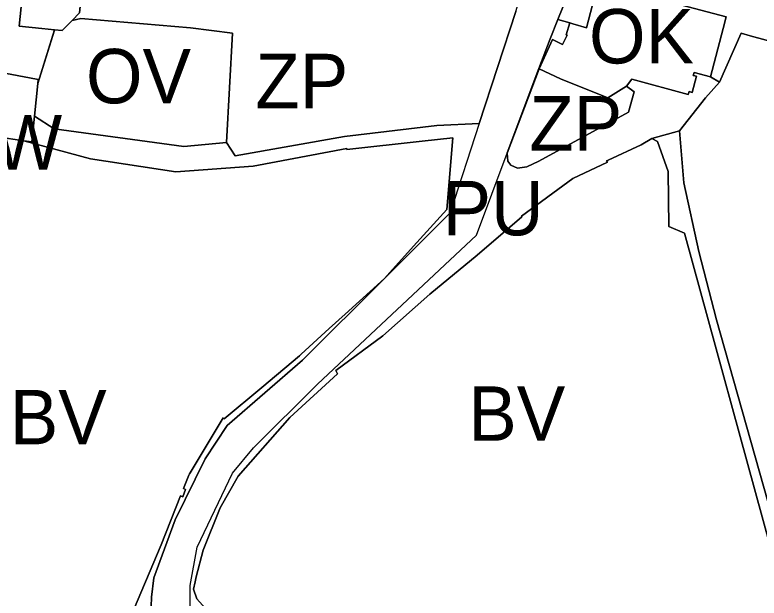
# Model space of a CAD drawing. Extents: x -555509 to -553005, y -1186756 to -1182560.
# Drawn here: x -554643.5 to -554451.9, y -1184692.3 to -1184542.3 of the extents above; entities that cross this region are included whole.
import ezdxf

# ---------------------------------------------------------------- set-up
doc = ezdxf.new("R2010")
doc.units = 0
for name, color, linetype in [('Level 15', 7, 'Continuous'), ('Level 59', 7, 'Continuous'), ('OBRYS_PLOCH', 7, 'Continuous'), ('stav_BV', 7, 'Continuous'), ('stav_DS', 7, 'Continuous'), ('stav_OK', 7, 'Continuous'), ('stav_OV', 7, 'Continuous'), ('stav_PU', 7, 'Continuous'), ('stav_TW', 7, 'Continuous'), ('stav_ZP', 7, 'Continuous')]:
    doc.layers.add(name, color=color, linetype=linetype)

msp = doc.modelspace()

# ---------------------------------------------------------------- linework, layer by layer
at = {"layer": 'Level 15'}
for p, q in [((-554462.1, -1184559.62), (-554464.39, -1184558.17)), ((-554633.37, -1184571.61), (-554638.48, -1184568.37)), ((-554600.05, -1184576.16), (-554633.37, -1184571.61)), ((-554479.48, -1184574.05), (-554472.4, -1184572.07)), ((-554589.05, -1184575.07), (-554600.05, -1184576.16))]:
    msp.add_line(p, q, dxfattribs=at)
for points in [[(-554431.8, -1184526.75), (-554468.49, -1184510.58), (-554512.11, -1184515.49), (-554501.82, -1184520.64), (-554490.14, -1184521.71), (-554496.01, -1184528.61), (-554497.62, -1184530.51), (-554502.44, -1184540.28), (-554503.73, -1184543.47), (-554500.65, -1184544.34), (-554499.87, -1184544.56), (-554496.29, -1184545.6), (-554493.28, -1184534.02), (-554460.33, -1184542.77), (-554461.09, -1184545.8), (-554464.39, -1184558.17), (-554462.1, -1184559.62), (-554456.48, -1184546.98), (-554454.18, -1184547.62), (-554450.06, -1184548.76)], [(-554503.73, -1184543.47), (-554502.44, -1184540.28), (-554497.62, -1184530.51), (-554496.01, -1184528.61), (-554490.14, -1184521.71), (-554501.82, -1184520.64)], [(-554647.61, -1184556.97), (-554637.95, -1184558.83), (-554637.55, -1184558.91), (-554637.65, -1184559.89), (-554633.35, -1184546.14), (-554636.54, -1184545.76), (-554642.43, -1184545.2), (-554641.91, -1184540.17)], [(-554514.53, -1184541.36), (-554523.93, -1184570.22), (-554534.86, -1184570.77), (-554558.65, -1184573.59), (-554586.8, -1184578.55), (-554589.05, -1184575.07)], [(-554503.73, -1184543.47), (-554505.72, -1184548.39), (-554508.61, -1184556.1), (-554508.55, -1184556.13)], [(-554508.55, -1184556.13), (-554508.61, -1184556.1), (-554505.72, -1184548.39), (-554503.73, -1184543.47)], [(-554500.65, -1184544.34), (-554503.73, -1184543.47)], [(-554502.51, -1184549.89), (-554501.31, -1184547.46), (-554501.53, -1184547.4), (-554500.65, -1184544.34)], [(-554508.55, -1184556.13), (-554505.11, -1184548.62), (-554502.51, -1184549.89)], [(-554511.73, -1184581.35), (-554514.1, -1184581.73), (-554515.78, -1184580.97), (-554516.62, -1184579.9), (-554516.77, -1184577.83), (-554508.55, -1184556.13)], [(-554464.39, -1184558.17), (-554468.61, -1184557.07), (-554468.82, -1184557.84), (-554468.04, -1184558.05), (-554469.15, -1184562.23), (-554469.92, -1184562.02), (-554470.11, -1184562.71), (-554484.65, -1184558.85), (-554486.05, -1184560.65)], [(-554472.4, -1184572.07), (-554465.7, -1184563.62), (-554462.1, -1184559.62)], [(-554486.05, -1184560.65), (-554484.04, -1184562.05), (-554485.49, -1184567.31), (-554508.61, -1184579.9), (-554511.73, -1184581.35)], [(-554638.48, -1184568.37), (-554639.13, -1184574.95), (-554641.22, -1184574.69)], [(-554479.48, -1184574.05), (-554472.4, -1184572.07)], [(-554445.16, -1184683.29), (-554462.84, -1184620.73), (-554467.41, -1184603.12), (-554471.22, -1184585.47), (-554472.4, -1184572.07), (-554479.48, -1184574.05), (-554478.02, -1184574.88), (-554475.32, -1184582.57), (-554475.11, -1184596.75), (-554471.13, -1184598.47), (-554448.83, -1184679.59)], [(-554641.22, -1184574.69), (-554624.01, -1184579.27), (-554602.06, -1184582.66), (-554582.17, -1184581.21), (-554558.05, -1184576.67), (-554558.06, -1184576.89), (-554538.67, -1184574.78), (-554530.71, -1184573.92), (-554532.3, -1184592.32), (-554540.01, -1184600.84), (-554546.31, -1184607.82)], [(-554548.81, -1184624.84), (-554536.63, -1184614.15), (-554524.49, -1184604.09), (-554512.94, -1184594.19), (-554513.06, -1184594.03), (-554499.86, -1184584.38), (-554490.9, -1184580.13), (-554491.15, -1184579.84), (-554490.74, -1184579.65), (-554482.25, -1184575.67), (-554479.48, -1184574.05)], [(-554546.31, -1184607.82), (-554548.33, -1184610.06), (-554558.48, -1184619.25), (-554562.59, -1184622.97), (-554569.82, -1184629.59), (-554570.26, -1184630), (-554579.97, -1184638.12), (-554589.61, -1184646.18), (-554589.92, -1184645.93), (-554598.4, -1184660.08), (-554598.56, -1184660.35), (-554598.7, -1184660.7), (-554600.08, -1184664.15), (-554599.55, -1184664.36), (-554600.31, -1184666.27), (-554600.84, -1184666.06), (-554605.86, -1184678.63), (-554613.93, -1184697.63)], [(-554560.44, -1184634.63), (-554560.91, -1184633.73), (-554548.81, -1184624.84)], [(-554586.04, -1184660.92), (-554572.69, -1184645.88), (-554560.44, -1184634.63)], [(-554596.64, -1184692.56), (-554597.52, -1184690.07), (-554597.1, -1184688.17), (-554596.82, -1184686.83), (-554595.05, -1184680.03), (-554590.62, -1184669.11), (-554586.04, -1184660.92)]]:
    msp.add_lwpolyline(points, dxfattribs=at)
at = {"layer": 'OBRYS_PLOCH'}
for p, q in [((-554503.73, -1184543.47), (-554502.44, -1184540.28)), ((-554514.53, -1184541.36), (-554523.93, -1184570.22)), ((-554628.76, -1184543.68), (-554631.37, -1184546.32)), ((-554505.72, -1184548.39), (-554503.73, -1184543.47)), ((-554633.44, -1184546.43), (-554637.65, -1184559.89)), ((-554633.35, -1184546.14), (-554633.44, -1184546.43)), ((-554631.37, -1184546.32), (-554633.35, -1184546.14)), ((-554508.61, -1184556.1), (-554505.72, -1184548.39)), ((-554516.75, -1184577.78), (-554508.61, -1184556.1)), ((-554503.03, -1184558.71), (-554508.55, -1184556.13)), ((-554638.48, -1184568.37), (-554637.65, -1184559.89)), ((-554637.65, -1184559.89), (-554638.48, -1184568.37)), ((-554638.48, -1184568.37), (-554633.37, -1184571.61)), ((-554633.37, -1184571.61), (-554600.05, -1184576.16)), ((-554523.93, -1184570.22), (-554531.42, -1184593.24)), ((-554523.93, -1184570.22), (-554523.93, -1184570.22)), ((-554652.51, -1184573.02), (-554641.22, -1184574.69)), ((-554641.22, -1184574.69), (-554652.51, -1184573.02)), ((-554600.05, -1184576.16), (-554589.05, -1184575.07)), ((-554524.68, -1184598.92), (-554516.77, -1184577.83)), ((-554531.42, -1184593.24), (-554548.33, -1184610.06)), ((-554565.59, -1184637.29), (-554524.68, -1184598.92)), ((-554548.33, -1184610.06), (-554569.5, -1184631.1)), ((-554569.5, -1184631.1), (-554548.33, -1184610.06)), ((-554569.5, -1184631.1), (-554588.87, -1184647.93)), ((-554588.87, -1184647.93), (-554569.5, -1184631.1)), ((-554582.04, -1184653.66), (-554565.59, -1184637.29)), ((-554588.87, -1184647.93), (-554594.53, -1184656.5)), ((-554594.53, -1184656.5), (-554588.87, -1184647.93)), ((-554587.48, -1184660.15), (-554582.04, -1184653.66)), ((-554594.53, -1184656.5), (-554602.26, -1184672.17)), ((-554602.26, -1184672.17), (-554594.53, -1184656.5)), ((-554596.62, -1184679.24), (-554587.48, -1184660.15)), ((-554602.26, -1184672.17), (-554607.73, -1184687.15)), ((-554607.73, -1184687.15), (-554602.26, -1184672.17)), ((-554598.38, -1184689.1), (-554596.62, -1184679.24)), ((-554607.73, -1184687.15), (-554608.32, -1184692.11)), ((-554608.32, -1184692.11), (-554607.73, -1184687.15)), ((-554598.29, -1184712.84), (-554598.38, -1184689.1)), ((-554608.32, -1184692.11), (-554612.53, -1184818.21)), ((-554612.53, -1184818.21), (-554608.32, -1184692.11))]:
    msp.add_line(p, q, dxfattribs=at)
for points in [[(-554589.05, -1184575.07), (-554586.8, -1184578.55), (-554558.65, -1184573.59), (-554534.86, -1184570.77), (-554523.93, -1184570.22), (-554514.53, -1184541.36), (-554512.28, -1184533.93), (-554512.36, -1184531.03), (-554513.65, -1184528.36), (-554517.85, -1184525.31), (-554520.44, -1184524.39), (-554525.17, -1184524.38), (-554532.88, -1184525.38), (-554538.03, -1184526.36), (-554562.63, -1184524.9), (-554588.8, -1184510.03), (-554591.92, -1184508.62), (-554607.58, -1184505.07), (-554615.1, -1184503.37), (-554622.88, -1184503.76)], [(-554623.31, -1184507.89), (-554626.87, -1184541.77), (-554628.76, -1184543.68), (-554626.5, -1184543.18), (-554598.31, -1184545.59)], [(-554647.61, -1184556.97), (-554637.95, -1184558.83), (-554637.55, -1184558.91), (-554637.65, -1184559.89), (-554633.35, -1184546.14), (-554636.54, -1184545.76), (-554642.43, -1184545.2), (-554641.91, -1184540.17)], [(-554598.31, -1184545.59), (-554626.5, -1184543.18), (-554628.76, -1184543.68)], [(-554598.31, -1184545.59), (-554587.46, -1184546.93), (-554589.05, -1184575.07)], [(-554589.05, -1184575.07), (-554587.46, -1184546.93), (-554598.31, -1184545.59)], [(-554390.85, -1184565.28), (-554405.31, -1184560.98), (-554419.37, -1184557.2), (-554419.64, -1184557.13), (-554429.38, -1184554.5), (-554433.92, -1184553.21), (-554450.06, -1184548.76), (-554454.18, -1184547.62), (-554456.48, -1184546.98), (-554462.1, -1184559.62), (-554465.7, -1184563.62), (-554472.4, -1184572.07), (-554471.22, -1184585.47), (-554467.41, -1184603.12), (-554462.84, -1184620.73), (-554445.16, -1184683.29), (-554442.42, -1184688.6)], [(-554508.55, -1184556.13), (-554516.77, -1184577.83), (-554516.62, -1184579.9), (-554515.78, -1184580.97), (-554514.1, -1184581.73), (-554511.73, -1184581.35)], [(-554637.65, -1184559.89), (-554637.55, -1184558.91), (-554637.95, -1184558.83), (-554647.61, -1184556.97), (-554650.55, -1184558.64), (-554651.57, -1184559.21), (-554652.04, -1184559.48), (-554653.22, -1184562.07), (-554654.9, -1184572.37), (-554652.51, -1184573.02)], [(-554486.05, -1184560.65), (-554490.82, -1184563.58), (-554503.03, -1184558.71)], [(-554511.73, -1184581.35), (-554508.61, -1184579.9), (-554485.49, -1184567.31), (-554484.04, -1184562.05), (-554486.05, -1184560.65)], [(-554641.22, -1184574.69), (-554639.13, -1184574.95), (-554638.48, -1184568.37)], [(-554479.48, -1184574.05), (-554472.4, -1184572.07)], [(-554546.31, -1184607.82), (-554540.01, -1184600.84), (-554532.3, -1184592.32), (-554530.71, -1184573.92), (-554538.67, -1184574.78), (-554558.06, -1184576.89), (-554558.05, -1184576.67), (-554582.17, -1184581.21), (-554602.06, -1184582.66), (-554624.01, -1184579.27), (-554641.22, -1184574.69)], [(-554448.83, -1184679.59), (-554471.13, -1184598.47), (-554475.11, -1184596.75), (-554475.32, -1184582.57), (-554478.02, -1184574.88), (-554479.48, -1184574.05), (-554482.25, -1184575.67), (-554490.74, -1184579.65), (-554491.15, -1184579.84), (-554490.9, -1184580.13), (-554499.86, -1184584.38), (-554513.06, -1184594.03), (-554512.94, -1184594.19), (-554524.49, -1184604.09), (-554536.63, -1184614.15), (-554548.81, -1184624.84)], [(-554516.77, -1184577.83), (-554516.77, -1184577.83), (-554516.75, -1184577.78)], [(-554613.93, -1184697.63), (-554605.86, -1184678.63), (-554600.84, -1184666.06), (-554600.31, -1184666.27), (-554599.55, -1184664.36), (-554600.08, -1184664.15), (-554598.7, -1184660.7), (-554598.56, -1184660.35), (-554598.4, -1184660.08), (-554589.92, -1184645.93), (-554589.61, -1184646.18), (-554579.97, -1184638.12), (-554570.26, -1184630), (-554569.82, -1184629.59), (-554562.59, -1184622.97), (-554558.48, -1184619.25), (-554548.33, -1184610.06), (-554546.31, -1184607.82)], [(-554548.33, -1184610.06), (-554558.48, -1184619.25), (-554562.59, -1184622.97), (-554569.82, -1184629.59), (-554570.26, -1184630), (-554579.97, -1184638.12), (-554589.61, -1184646.18), (-554589.92, -1184645.93), (-554598.4, -1184660.08), (-554598.56, -1184660.35), (-554598.7, -1184660.7), (-554600.08, -1184664.15), (-554599.55, -1184664.36), (-554600.31, -1184666.27), (-554600.84, -1184666.06), (-554605.86, -1184678.63), (-554613.93, -1184697.63)], [(-554548.81, -1184624.84), (-554560.91, -1184633.73), (-554560.44, -1184634.63)], [(-554560.44, -1184634.63), (-554572.69, -1184645.88), (-554586.04, -1184660.92), (-554590.62, -1184669.11), (-554595.05, -1184680.03), (-554596.82, -1184686.83), (-554597.1, -1184688.17), (-554597.52, -1184690.07), (-554596.64, -1184692.56), (-554593.79, -1184695.74), (-554585.63, -1184701.15), (-554578.08, -1184702.78), (-554576.09, -1184703.2), (-554576.53, -1184705.42), (-554570.43, -1184706.67), (-554570.18, -1184704.85), (-554569.77, -1184702.04), (-554563.16, -1184703.5), (-554556.64, -1184704.93), (-554556.06, -1184706.7), (-554540.86, -1184705.8), (-554529.94, -1184704)]]:
    msp.add_lwpolyline(points, dxfattribs=at)
for points in [[(-554633.35, -1184546.14), (-554631.37, -1184546.32), (-554628.76, -1184543.68), (-554626.87, -1184541.77), (-554623.41, -1184508.79), (-554633.33, -1184509.7), (-554637.02, -1184517), (-554639.47, -1184516.74), (-554640.14, -1184523.18), (-554641.91, -1184540.17), (-554642.43, -1184545.2), (-554636.54, -1184545.76)], [(-554490.82, -1184563.58), (-554486.05, -1184560.65), (-554484.65, -1184558.85), (-554470.11, -1184562.71), (-554469.92, -1184562.02), (-554469.15, -1184562.23), (-554468.04, -1184558.05), (-554468.82, -1184557.84), (-554468.61, -1184557.07), (-554464.39, -1184558.17), (-554461.09, -1184545.8), (-554460.33, -1184542.77), (-554493.28, -1184534.02), (-554496.29, -1184545.6), (-554499.87, -1184544.56), (-554500.65, -1184544.34), (-554501.53, -1184547.4), (-554501.31, -1184547.46), (-554502.51, -1184549.89), (-554505.11, -1184548.62), (-554508.55, -1184556.13), (-554503.03, -1184558.71)]]:
    msp.add_lwpolyline(points, close=True, dxfattribs=at)
at = {"layer": 'stav_BV'}
msp.add_line((-554641.22, -1184574.69), (-554652.51, -1184573.02), dxfattribs=at)
for points in [[(-554390.85, -1184565.28), (-554405.31, -1184560.98), (-554419.37, -1184557.2), (-554419.64, -1184557.13), (-554429.38, -1184554.5), (-554433.92, -1184553.21), (-554450.06, -1184548.76), (-554454.18, -1184547.62), (-554456.48, -1184546.98), (-554462.1, -1184559.62), (-554465.7, -1184563.62), (-554472.4, -1184572.07), (-554471.22, -1184585.47), (-554467.41, -1184603.12), (-554462.84, -1184620.73), (-554445.16, -1184683.29), (-554442.42, -1184688.6)], [(-554546.31, -1184607.82), (-554540.01, -1184600.84), (-554532.3, -1184592.32), (-554530.71, -1184573.92), (-554538.67, -1184574.78), (-554558.06, -1184576.89), (-554558.05, -1184576.67), (-554582.17, -1184581.21), (-554602.06, -1184582.66), (-554624.01, -1184579.27), (-554641.22, -1184574.69)], [(-554448.83, -1184679.59), (-554471.13, -1184598.47), (-554475.11, -1184596.75), (-554475.32, -1184582.57), (-554478.02, -1184574.88), (-554479.48, -1184574.05), (-554482.25, -1184575.67), (-554490.74, -1184579.65), (-554491.15, -1184579.84), (-554490.9, -1184580.13), (-554499.86, -1184584.38), (-554513.06, -1184594.03), (-554512.94, -1184594.19), (-554524.49, -1184604.09), (-554536.63, -1184614.15), (-554548.81, -1184624.84)], [(-554613.93, -1184697.63), (-554605.86, -1184678.63), (-554600.84, -1184666.06), (-554600.31, -1184666.27), (-554599.55, -1184664.36), (-554600.08, -1184664.15), (-554598.7, -1184660.7), (-554598.56, -1184660.35), (-554598.4, -1184660.08), (-554589.92, -1184645.93), (-554589.61, -1184646.18), (-554579.97, -1184638.12), (-554570.26, -1184630), (-554569.82, -1184629.59), (-554562.59, -1184622.97), (-554558.48, -1184619.25), (-554548.33, -1184610.06), (-554546.31, -1184607.82)], [(-554548.81, -1184624.84), (-554560.91, -1184633.73), (-554560.44, -1184634.63)], [(-554560.44, -1184634.63), (-554572.69, -1184645.88), (-554586.04, -1184660.92), (-554590.62, -1184669.11), (-554595.05, -1184680.03), (-554596.82, -1184686.83), (-554597.1, -1184688.17), (-554597.52, -1184690.07), (-554596.64, -1184692.56), (-554593.79, -1184695.74), (-554585.63, -1184701.15), (-554578.08, -1184702.78), (-554576.09, -1184703.2), (-554576.53, -1184705.42), (-554570.43, -1184706.67), (-554570.18, -1184704.85), (-554569.77, -1184702.04), (-554563.16, -1184703.5), (-554556.64, -1184704.93), (-554556.06, -1184706.7), (-554540.86, -1184705.8), (-554529.94, -1184704)]]:
    msp.add_lwpolyline(points, dxfattribs=at)
at = {"layer": 'stav_DS'}
for p, q in [((-554505.72, -1184548.39), (-554502.44, -1184540.28)), ((-554508.61, -1184556.1), (-554505.72, -1184548.39)), ((-554516.75, -1184577.78), (-554508.61, -1184556.1)), ((-554523.93, -1184570.22), (-554531.42, -1184593.24)), ((-554524.68, -1184598.92), (-554516.77, -1184577.83)), ((-554531.42, -1184593.24), (-554548.33, -1184610.06)), ((-554565.59, -1184637.29), (-554524.68, -1184598.92)), ((-554548.33, -1184610.06), (-554569.5, -1184631.1)), ((-554569.5, -1184631.1), (-554588.87, -1184647.93)), ((-554582.04, -1184653.66), (-554565.59, -1184637.29)), ((-554588.87, -1184647.93), (-554594.53, -1184656.5)), ((-554587.48, -1184660.15), (-554582.04, -1184653.66)), ((-554594.53, -1184656.5), (-554602.26, -1184672.17)), ((-554596.62, -1184679.24), (-554587.48, -1184660.15)), ((-554602.26, -1184672.17), (-554607.73, -1184687.15)), ((-554598.38, -1184689.1), (-554596.62, -1184679.24)), ((-554607.73, -1184687.15), (-554608.32, -1184692.11)), ((-554598.29, -1184712.84), (-554598.38, -1184689.1)), ((-554608.32, -1184692.11), (-554612.53, -1184818.21))]:
    msp.add_line(p, q, dxfattribs=at)
for points in [[(-554514.53, -1184541.36), (-554523.93, -1184570.22), (-554523.93, -1184570.22)], [(-554516.77, -1184577.83), (-554516.77, -1184577.83), (-554516.75, -1184577.78)]]:
    msp.add_lwpolyline(points, dxfattribs=at)
at = {"layer": 'stav_OK'}
for points in [[(-554633.35, -1184546.14), (-554631.37, -1184546.32), (-554628.76, -1184543.68), (-554626.87, -1184541.77), (-554623.41, -1184508.79), (-554633.33, -1184509.7), (-554637.02, -1184517), (-554639.47, -1184516.74), (-554640.14, -1184523.18), (-554641.91, -1184540.17), (-554642.43, -1184545.2), (-554636.54, -1184545.76)], [(-554490.82, -1184563.58), (-554486.05, -1184560.65), (-554484.65, -1184558.85), (-554470.11, -1184562.71), (-554469.92, -1184562.02), (-554469.15, -1184562.23), (-554468.04, -1184558.05), (-554468.82, -1184557.84), (-554468.61, -1184557.07), (-554464.39, -1184558.17), (-554461.09, -1184545.8), (-554460.33, -1184542.77), (-554493.28, -1184534.02), (-554496.29, -1184545.6), (-554499.87, -1184544.56), (-554500.65, -1184544.34), (-554501.53, -1184547.4), (-554501.31, -1184547.46), (-554502.51, -1184549.89), (-554505.11, -1184548.62), (-554508.55, -1184556.13), (-554503.03, -1184558.71)]]:
    msp.add_lwpolyline(points, close=True, dxfattribs=at)
at = {"layer": 'stav_OV'}
for p, q in [((-554628.76, -1184543.68), (-554631.37, -1184546.32)), ((-554633.44, -1184546.43), (-554637.65, -1184559.89)), ((-554633.35, -1184546.14), (-554633.44, -1184546.43)), ((-554631.37, -1184546.32), (-554633.35, -1184546.14)), ((-554637.65, -1184559.89), (-554638.48, -1184568.37)), ((-554638.48, -1184568.37), (-554633.37, -1184571.61)), ((-554633.37, -1184571.61), (-554600.05, -1184576.16)), ((-554600.05, -1184576.16), (-554589.05, -1184575.07))]:
    msp.add_line(p, q, dxfattribs=at)
for points in [[(-554598.31, -1184545.59), (-554626.5, -1184543.18), (-554628.76, -1184543.68)], [(-554589.05, -1184575.07), (-554587.46, -1184546.93), (-554598.31, -1184545.59)]]:
    msp.add_lwpolyline(points, dxfattribs=at)
at = {"layer": 'stav_PU'}
for p, q in [((-554500.65, -1184544.34), (-554499.87, -1184544.56)), ((-554464.39, -1184558.17), (-554468.61, -1184557.07)), ((-554633.37, -1184571.61), (-554638.48, -1184568.37)), ((-554600.05, -1184576.16), (-554633.37, -1184571.61)), ((-554589.05, -1184575.07), (-554600.05, -1184576.16)), ((-554596.64, -1184692.56), (-554597.52, -1184690.07))]:
    msp.add_line(p, q, dxfattribs=at)
for points in [[(-554499.87, -1184544.56), (-554496.29, -1184545.6), (-554493.28, -1184534.02), (-554460.33, -1184542.77), (-554461.09, -1184545.8), (-554464.39, -1184558.17)], [(-554647.61, -1184556.97), (-554637.95, -1184558.83), (-554637.55, -1184558.91), (-554637.65, -1184559.89), (-554633.35, -1184546.14), (-554636.54, -1184545.76), (-554642.43, -1184545.2), (-554641.91, -1184540.17)], [(-554514.53, -1184541.36), (-554523.93, -1184570.22), (-554534.86, -1184570.77), (-554558.65, -1184573.59), (-554586.8, -1184578.55), (-554589.05, -1184575.07)], [(-554502.51, -1184549.89), (-554501.31, -1184547.46), (-554501.53, -1184547.4), (-554500.65, -1184544.34)], [(-554508.55, -1184556.13), (-554505.11, -1184548.62), (-554502.51, -1184549.89)], [(-554462.1, -1184559.62), (-554456.48, -1184546.98), (-554454.18, -1184547.62), (-554450.06, -1184548.76), (-554433.92, -1184553.21), (-554429.38, -1184554.5), (-554419.64, -1184557.13)], [(-554511.73, -1184581.35), (-554514.1, -1184581.73), (-554515.78, -1184580.97), (-554516.62, -1184579.9), (-554516.77, -1184577.83), (-554508.55, -1184556.13)], [(-554468.61, -1184557.07), (-554468.82, -1184557.84), (-554468.04, -1184558.05), (-554469.15, -1184562.23), (-554469.92, -1184562.02), (-554470.11, -1184562.71), (-554484.65, -1184558.85), (-554486.05, -1184560.65)], [(-554472.4, -1184572.07), (-554465.7, -1184563.62), (-554462.1, -1184559.62)], [(-554486.05, -1184560.65), (-554484.04, -1184562.05), (-554485.49, -1184567.31), (-554508.61, -1184579.9), (-554511.73, -1184581.35)], [(-554638.48, -1184568.37), (-554639.13, -1184574.95), (-554641.22, -1184574.69)], [(-554479.48, -1184574.05), (-554472.4, -1184572.07)], [(-554445.16, -1184683.29), (-554462.84, -1184620.73), (-554467.41, -1184603.12), (-554471.22, -1184585.47), (-554472.4, -1184572.07)], [(-554641.22, -1184574.69), (-554624.01, -1184579.27), (-554602.06, -1184582.66), (-554582.17, -1184581.21), (-554558.05, -1184576.67), (-554558.06, -1184576.89), (-554538.67, -1184574.78), (-554530.71, -1184573.92), (-554532.3, -1184592.32), (-554540.01, -1184600.84), (-554546.31, -1184607.82)], [(-554548.81, -1184624.84), (-554536.63, -1184614.15), (-554524.49, -1184604.09), (-554512.94, -1184594.19), (-554513.06, -1184594.03), (-554499.86, -1184584.38), (-554490.9, -1184580.13), (-554491.15, -1184579.84), (-554490.74, -1184579.65), (-554482.25, -1184575.67), (-554479.48, -1184574.05)], [(-554479.48, -1184574.05), (-554478.02, -1184574.88), (-554475.32, -1184582.57), (-554475.11, -1184596.75), (-554471.13, -1184598.47), (-554448.83, -1184679.59)], [(-554546.31, -1184607.82), (-554548.33, -1184610.06), (-554558.48, -1184619.25), (-554562.59, -1184622.97), (-554569.82, -1184629.59), (-554570.26, -1184630), (-554579.97, -1184638.12), (-554589.61, -1184646.18), (-554589.92, -1184645.93), (-554598.4, -1184660.08), (-554598.56, -1184660.35), (-554598.7, -1184660.7), (-554600.08, -1184664.15), (-554599.55, -1184664.36), (-554600.31, -1184666.27), (-554600.84, -1184666.06), (-554605.86, -1184678.63), (-554613.93, -1184697.63)], [(-554560.44, -1184634.63), (-554560.91, -1184633.73), (-554548.81, -1184624.84)], [(-554586.04, -1184660.92), (-554572.69, -1184645.88), (-554560.44, -1184634.63)], [(-554597.52, -1184690.07), (-554597.1, -1184688.17), (-554596.82, -1184686.83), (-554595.05, -1184680.03), (-554590.62, -1184669.11), (-554586.04, -1184660.92)]]:
    msp.add_lwpolyline(points, dxfattribs=at)
at = {"layer": 'stav_TW'}
for p, q in [((-554638.48, -1184568.37), (-554637.65, -1184559.89)), ((-554652.51, -1184573.02), (-554641.22, -1184574.69))]:
    msp.add_line(p, q, dxfattribs=at)
for points in [[(-554637.65, -1184559.89), (-554637.55, -1184558.91), (-554637.95, -1184558.83), (-554647.61, -1184556.97), (-554650.55, -1184558.64), (-554651.57, -1184559.21), (-554652.04, -1184559.48), (-554653.22, -1184562.07), (-554654.9, -1184572.37), (-554652.51, -1184573.02)], [(-554641.22, -1184574.69), (-554639.13, -1184574.95), (-554638.48, -1184568.37)]]:
    msp.add_lwpolyline(points, dxfattribs=at)
at = {"layer": 'stav_ZP'}
msp.add_line((-554503.03, -1184558.71), (-554508.55, -1184556.13), dxfattribs=at)
for points in [[(-554589.05, -1184575.07), (-554586.8, -1184578.55), (-554558.65, -1184573.59), (-554534.86, -1184570.77), (-554523.93, -1184570.22), (-554514.53, -1184541.36), (-554512.28, -1184533.93), (-554512.36, -1184531.03), (-554513.65, -1184528.36), (-554517.85, -1184525.31), (-554520.44, -1184524.39), (-554525.17, -1184524.38), (-554532.88, -1184525.38), (-554538.03, -1184526.36), (-554562.63, -1184524.9), (-554588.8, -1184510.03), (-554591.92, -1184508.62), (-554607.58, -1184505.07), (-554615.1, -1184503.37), (-554622.88, -1184503.76)], [(-554623.31, -1184507.89), (-554626.87, -1184541.77), (-554628.76, -1184543.68), (-554626.5, -1184543.18), (-554598.31, -1184545.59)], [(-554598.31, -1184545.59), (-554587.46, -1184546.93), (-554589.05, -1184575.07)], [(-554508.55, -1184556.13), (-554516.77, -1184577.83), (-554516.62, -1184579.9), (-554515.78, -1184580.97), (-554514.1, -1184581.73), (-554511.73, -1184581.35)], [(-554486.05, -1184560.65), (-554490.82, -1184563.58), (-554503.03, -1184558.71)], [(-554511.73, -1184581.35), (-554508.61, -1184579.9), (-554485.49, -1184567.31), (-554484.04, -1184562.05), (-554486.05, -1184560.65)]]:
    msp.add_lwpolyline(points, dxfattribs=at)

# ---------------------------------------------------------------- texts
at = {"layer": 'Level 59'}
for s, p in [('OK', (-554495.68, -1184554.76)), ('OV', (-554625.21, -1184565.03)), ('ZP', (-554581.6, -1184566.28)), ('ZP', (-554511.06, -1184577.18)), ('TW', (-554660.47, -1184582.07)), ('PU', (-554533.39, -1184599)), ('BV', (-554644.84, -1184652.76)), ('BV', (-554526.77, -1184651.85))]:
    msp.add_text(s, height=14, dxfattribs=at).set_placement(p)

doc.saveas('drawing.dxf')
